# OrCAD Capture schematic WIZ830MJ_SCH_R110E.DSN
size B; title: WIZ830MJ; rev: REV.1.1
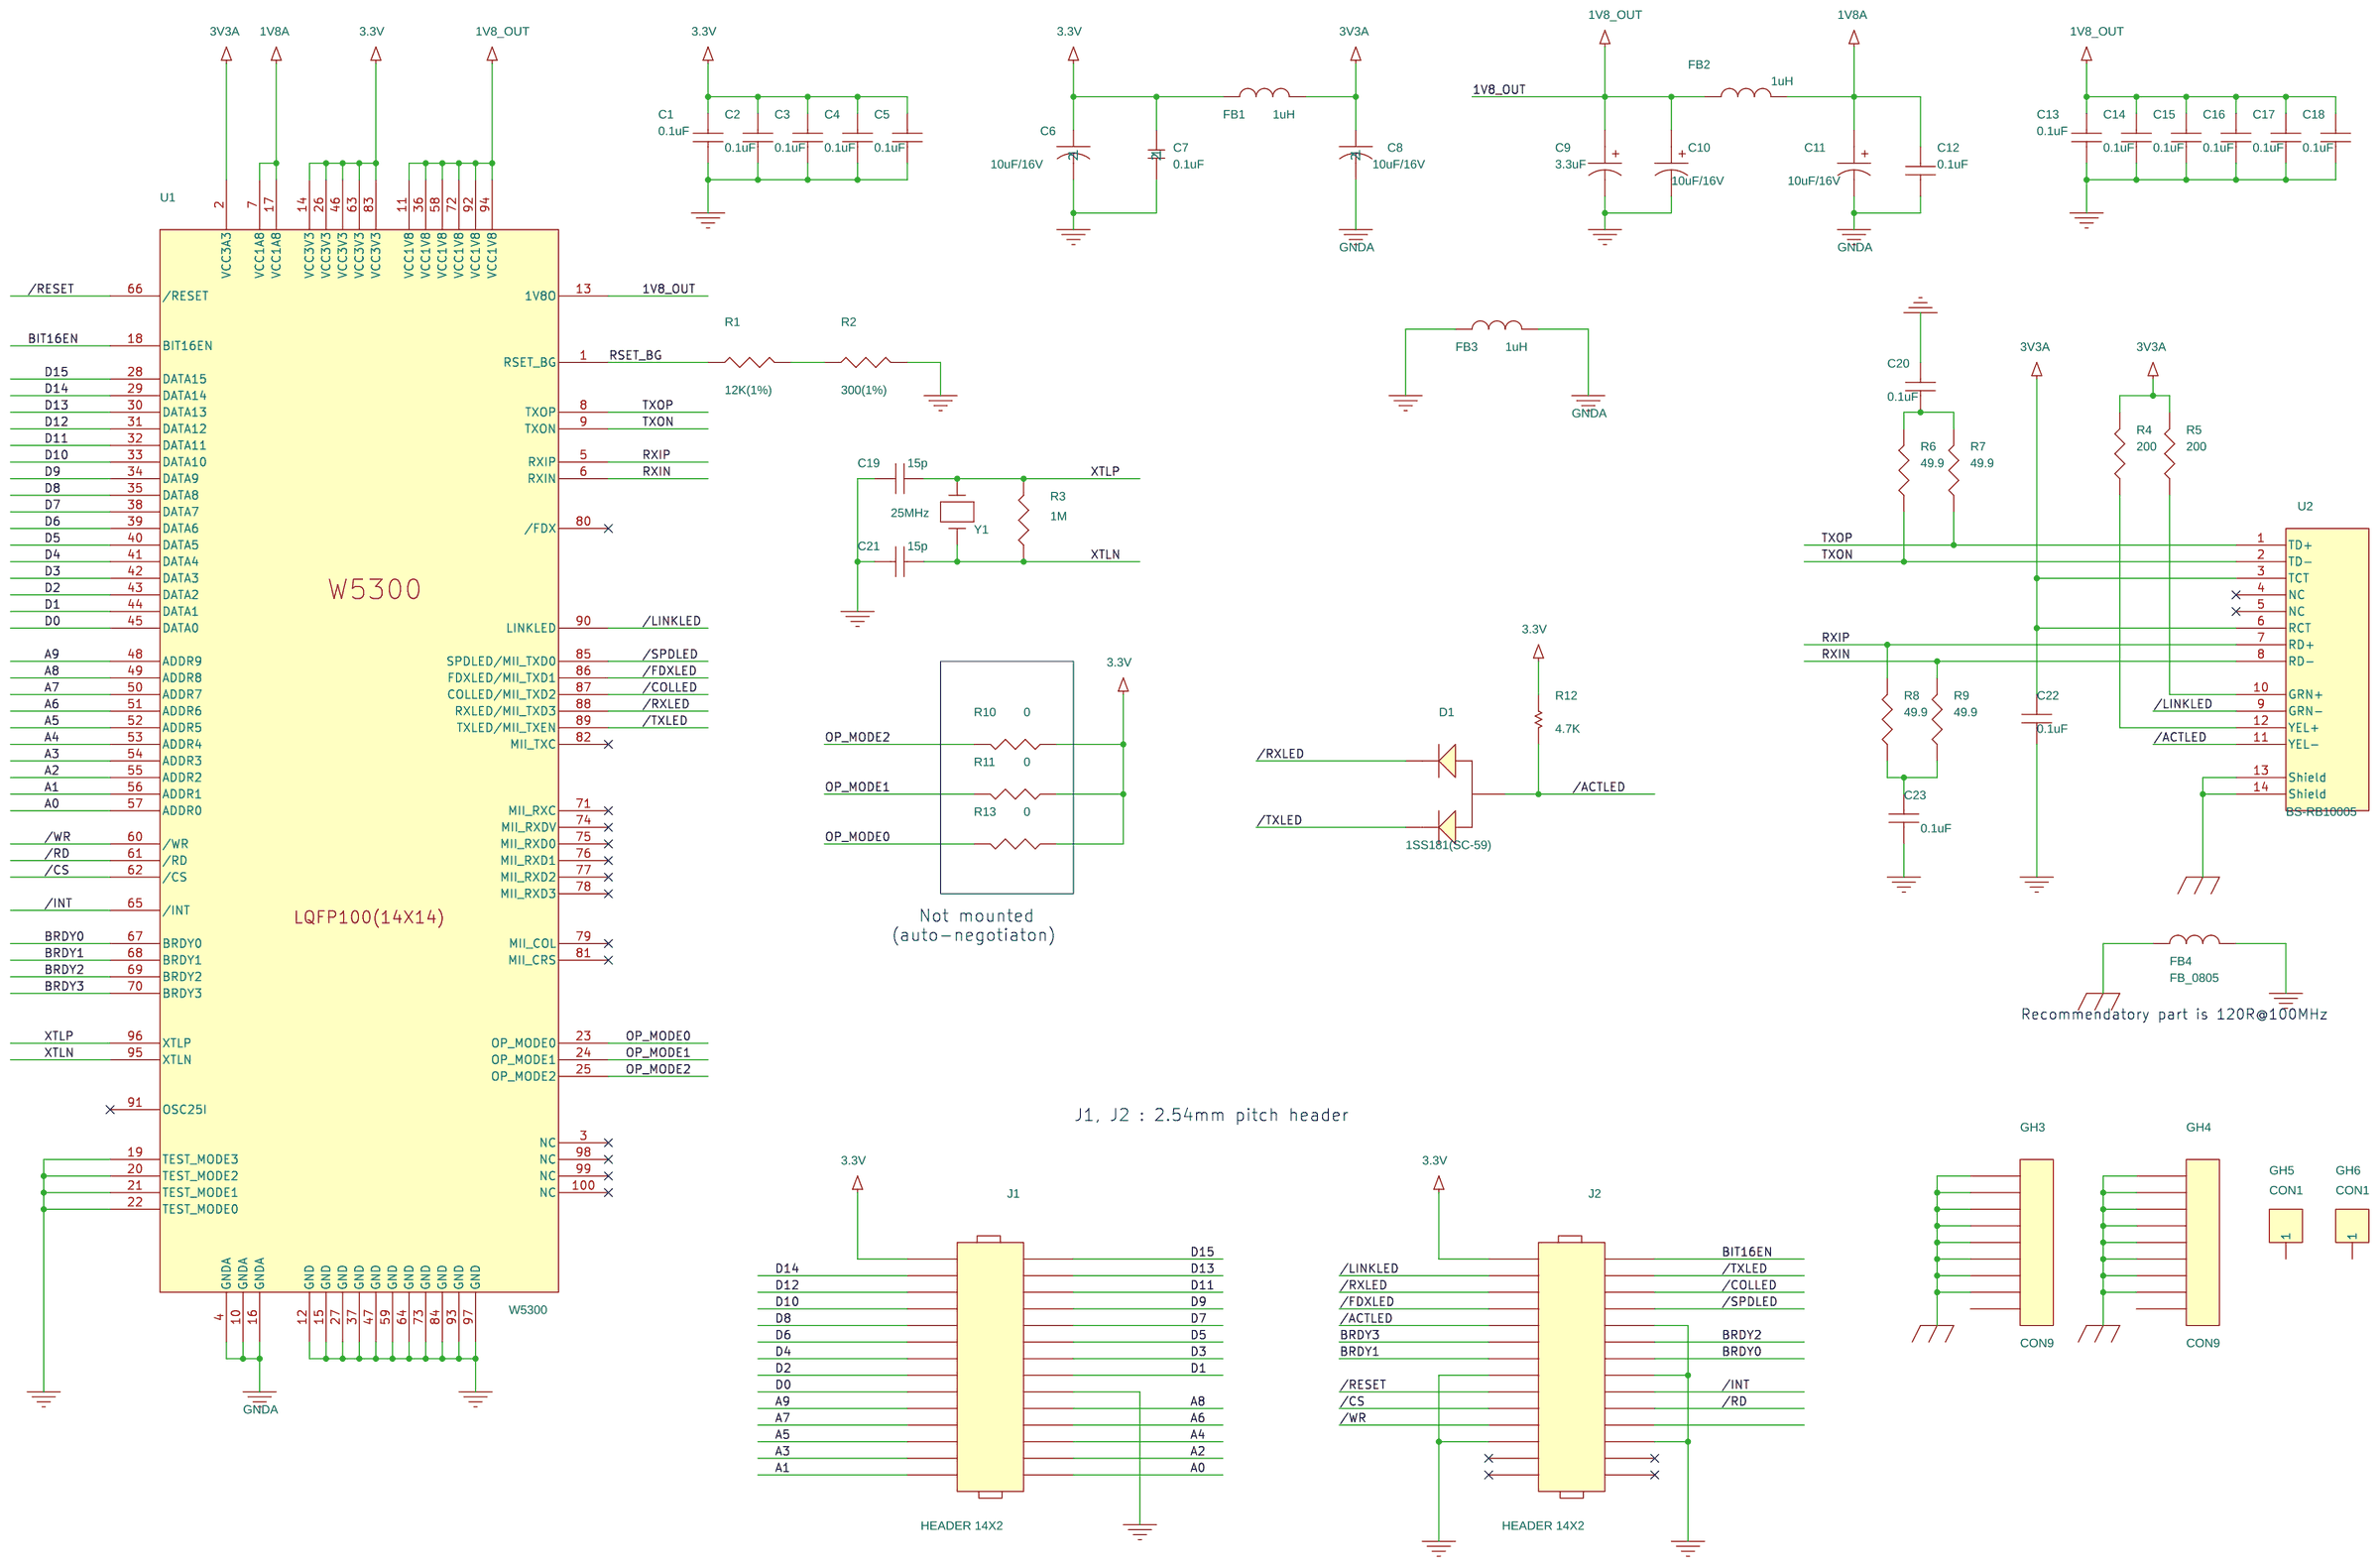
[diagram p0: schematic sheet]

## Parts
C1  0.1uF
C2  0.1uF
C3  0.1uF
C4  0.1uF
C5  0.1uF
C6  10uF/16V  [CAP\B\3528]
C7  0.1uF  [C0603]
C8  10uF/16V  [CAP\A\3216]
C9  3.3uF
C10  10uF/16V
C11  10uF/16V
C12  0.1uF
C13  0.1uF
C14  0.1uF
C15  0.1uF
C16  0.1uF
C17  0.1uF
C18  0.1uF
C19  15p
C20  0.1uF
C21  15p
C22  0.1uF
C23  0.1uF
D1  1SS181(SC-59)
FB1  1uH  [L0805]
FB2  1uH  [L0805]
FB3  1uH  [L0805]
FB4  FB_0805  [L0805]
GH3  CON9
GH4  CON9
GH5  CON1
GH6  CON1
J1  HEADER 14X2
J2  HEADER 14X2
R1  12K(1%)
R2  300(1%)
R3  1M
R4  200
R5  200
R6  49.9
R7  49.9
R8  49.9
R9  49.9
R10  0
R11  0
R12  4.7K
R13  0
U1  W5300
U2  BS-RB10005
Y1  25MHz

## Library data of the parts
C1-C5 C12-C23 = CAP_NP
C6 = CAP_4.7uF_B
C7 = CAP_0.01uF_0603
C8 = CAP_1uF_A
C9-C11 = CP
D1 = 1SS181
FB1-FB4 = FB_0805
GH3 GH4 = CON9
GH5 GH6 = CON1
J1 J2 = HEADER_14X2
R1-R11 R13 = R
R12 = SMALL_R1
U1 = W5300
U2 = P65-101-11A7_0
Y1 = CRYSTAL

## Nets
1V8A: C11.1 C12.1 FB2.2 U1.7(VCC1A8) U1.17(VCC1A8)
1V8D: C9.1 C10.1 C13.1 C14.1 C15.1 C16.1 C17.1 C18.1 FB2.1 U1.11(VCC1V8) U1.13(1V8O) U1.36(VCC1V8) U1.58(VCC1V8) U1.72(VCC1V8) U1.92(VCC1V8) U1.94(VCC1V8)
3.3V: C1.1 C2.1 C3.1 C4.1 C5.1 C6.1 C7.1 FB1.1 J1.1 J2.1 R10.1 R11.1 R12.1 R13.1 U1.14(VCC3V3) U1.26(VCC3V3) U1.46(VCC3V3) U1.63(VCC3V3) U1.83(VCC3V3)
3V3A: C8.1 C22.1 FB1.2 R4.2 R5.2 U1.2(VCC3A3) U2.3(TCT) U2.6(RCT)
GND: C1.2 C2.2 C3.2 C4.2 C5.2 C6.2 C7.2 C9.2 C10.2 C13.2 C14.2 C15.2 C16.2 C17.2 C18.2 C19.2 C20.1 C21.2 C22.2 C23.2 FB3.1 FB4.2 J1.18 J2.10 J2.15 J2.16 J2.23 J2.24 R2.2 U1.12(GND) U1.15(GND) U1.19(TEST_MODE3) U1.20(TEST_MODE2) U1.21(TEST_MODE1) U1.22(TEST_MODE0) U1.27(GND) U1.37(GND) U1.47(GND) U1.59(GND) U1.64(GND) U1.73(GND) U1.84(GND) U1.93(GND) U1.97(GND)
GND_EARTH: FB4.1 GH3.1 GH3.2 GH3.3 GH3.4 GH3.5 GH3.6 GH3.7 GH3.8 GH4.1 GH4.2 GH4.3 GH4.4 GH4.5 GH4.6 GH4.7 GH4.8 U2.13(Shield) U2.14(Shield)
GNDA: C8.2 C11.2 C12.2 FB3.2 U1.4(GNDA) U1.10(GNDA) U1.16(GNDA)
/ACTLED: D1.3 J2.9 R12.2 U2.11(YEL-)
/COLLED: J2.6 U1.87(COLLED/MII_TXD2)
/CS: J2.19 U1.62(/CS)
/FDXLED: J2.7 U1.86(FDXLED/MII_TXD1)
/INT: J2.18 U1.65(/INT)
/LINKLED: J2.3 U1.90(LINKLED) U2.9(GRN-)
/RD: J2.20 U1.61(/RD)
/RESET: J2.17 U1.66(/RESET)
/RXLED: D1.1 J2.5 U1.88(RXLED/MII_TXD3)
/SPDLED: J2.8 U1.85(SPDLED/MII_TXD0)
/TXLED: D1.2 J2.4 U1.89(TXLED/MII_TXEN)
/WR: J2.21 U1.60(/WR)
A0: J1.28 U1.57(ADDR0)
A1: J1.27 U1.56(ADDR1)
A2: J1.26 U1.55(ADDR2)
A3: J1.25 U1.54(ADDR3)
A4: J1.24 U1.53(ADDR4)
A5: J1.23 U1.52(ADDR5)
A6: J1.22 U1.51(ADDR6)
A7: J1.21 U1.50(ADDR7)
A8: J1.20 U1.49(ADDR8)
A9: J1.19 U1.48(ADDR9)
BIT16EN: J2.2 U1.18(BIT16EN)
BRDY0: J2.14 U1.67(BRDY0)
BRDY1: J2.13 U1.68(BRDY1)
BRDY2: J2.12 U1.69(BRDY2)
BRDY3: J2.11 U1.70(BRDY3)
D0: J1.17 U1.45(DATA0)
D1: J1.16 U1.44(DATA1)
D2: J1.15 U1.43(DATA2)
D3: J1.14 U1.42(DATA3)
D4: J1.13 U1.41(DATA4)
D5: J1.12 U1.40(DATA5)
D6: J1.11 U1.39(DATA6)
D7: J1.10 U1.38(DATA7)
D8: J1.9 U1.35(DATA8)
D9: J1.8 U1.34(DATA9)
D10: J1.7 U1.33(DATA10)
D11: J1.6 U1.32(DATA11)
D12: J1.5 U1.31(DATA12)
D13: J1.4 U1.30(DATA13)
D14: J1.3 U1.29(DATA14)
D15: J1.2 U1.28(DATA15)
OP_MODE0: R13.2 U1.23(OP_MODE0)
OP_MODE1: R11.2 U1.24(OP_MODE1)
OP_MODE2: R10.2 U1.25(OP_MODE2)
RSET_BG: R1.1 U1.1(RSET_BG)
RXIN: R9.2 U1.6(RXIN) U2.8(RD-)
RXIP: R8.2 U1.5(RXIP) U2.7(RD+)
TXON: R6.1 U1.9(TXON) U2.2(TD-)
TXOP: R7.1 U1.8(TXOP) U2.1(TD+)
XTLN: C21.1 R3.1 U1.95(XTLN) Y1.2
XTLP: C19.1 R3.2 U1.96(XTLP) Y1.1
N16727991: R1.2 R2.1
N16793958: C23.1 R8.1 R9.1
N16794088: C20.2 R6.2 R7.2
N16794205: R5.1 U2.10(GRN+)
N16794210: R4.1 U2.12(YEL+)

Not connected (* = marked no-connect by the designer): GH3 9; GH4 9; GH5 1; GH6 1; J2 22 25* 26* 27* 28*; U1 3(NC)* 71(MII_RXC)* 74(MII_RXDV)* 75(MII_RXD0)* 76(MII_RXD1)* 77(MII_RXD2)* 78(MII_RXD3)* 79(MII_COL)* 80(/FDX)* 81(MII_CRS)* 82(MII_TXC)* 91(OSC25I)* 98(NC)* 99(NC)* 100(NC)*; U2 4(NC)* 5(NC)*

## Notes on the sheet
- Not mounted
  (auto-negotiaton)
- Recommendatory part is 120R@100MHz
- J1, J2 : 2.54mm pitch header
